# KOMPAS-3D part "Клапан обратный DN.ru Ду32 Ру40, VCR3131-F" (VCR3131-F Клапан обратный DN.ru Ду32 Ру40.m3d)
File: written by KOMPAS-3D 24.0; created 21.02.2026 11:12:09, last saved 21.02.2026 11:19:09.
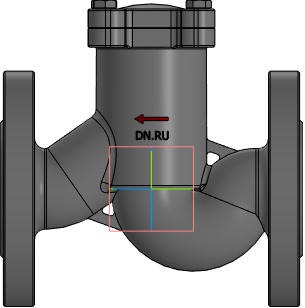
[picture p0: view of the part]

Document properties: Автор: R2D2; Полное имя файла: VCR3131-F Клапан обратный DN.ru Ду32 Ру40.cdw

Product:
- Part/product: Клапан обратный DN.ru Ду32 Ру40  | designation VCR3131-F
    Масса: 7
    Раздел спецификации: Прочие изделия
    Форматы листов документа: A3
    Примечание: D100-04039
    additional columns: D100-04039

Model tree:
1. Операция без истории:1

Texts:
  VCR3131-F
